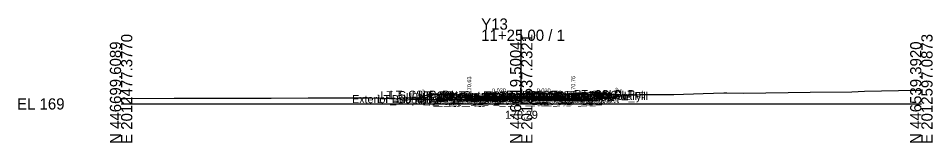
# Model space of a CAD drawing. Extents: x -26 to 1403, y -10 to 4517.
# Drawn here: x -25.7 to 202.8, y 2490.3 to 2521.4 of the extents above; entities that cross this region are included whole.
import ezdxf

# ---------------------------------------------------------------- set-up
doc = ezdxf.new("R2010")
doc.units = 0
for name, color, linetype in [('Default', 7, 'Continuous'), ('Exist CMT Pavement', 7, 'Continuous'), ('Exist Cross Section Cell', 7, 'Continuous'), ('Exist XS Center Line Elevation Label', 7, 'Continuous'), ('Exist XS Ground Line', 7, 'Continuous'), ('Prop CMT Conc Surface', 7, 'Continuous'), ('Prop CMT Concrete Structures', 7, 'Continuous'), ('Prop CMT Pvmt Course 1', 7, 'Continuous'), ('Prop CMT Pvmt Course 1 CG', 7, 'Continuous'), ('Prop CMT Pvmt Course 1 Wedge', 7, 'Continuous'), ('Prop CMT Pvmt Course 2', 7, 'Continuous'), ('Prop CMT Pvmt Course 2 Wedge', 7, 'Continuous'), ('Prop CMT Pvmt Course 3', 7, 'Continuous'), ('Prop CMT Pvmt Course 3 Wedge', 7, 'Continuous'), ('Prop CMT Pvmt Surface', 7, 'Continuous'), ('Prop CMT Pvmt Wedge Surface 1', 7, 'Continuous'), ('Prop CMT Pvmt Wedge Surface 2', 7, 'Continuous'), ('Prop CMT Pvmt Wedge Surface 3', 7, 'Continuous'), ('Prop CMT Slope Grass', 7, 'Continuous'), ('Prop CMT Subgrade Earthwork', 7, 'Continuous'), ('Prop XS Earthwork Shape', 7, 'Continuous'), ('Prop XS Hydro Elevations', 7, 'Continuous'), ('Prop XS SE Text', 7, 'Continuous'), ('Prop XS Side Slope Text', 7, 'Continuous'), ('Scratch_Level_0', 7, 'Continuous')]:
    doc.layers.add(name, color=color, linetype=linetype)

msp = doc.modelspace()

# ---------------------------------------------------------------- linework, layer by layer
at = {"layer": 'Exist CMT Pavement'}
for points in [[(100, 2501.29), (99.91, 2501.29), (94.09, 2501.06), (90, 2500.86)], [(100, 2501.29), (105.87, 2501.1), (110, 2500.94)]]:
    msp.add_lwpolyline(points, dxfattribs=at)
at = {"layer": 'Exist Cross Section Cell'}
for p, q in [((100, 2500), (100, 2518.56)), ((0, 2500), (100, 2500)), ((100, 2500), (200, 2500))]:
    msp.add_line(p, q, dxfattribs=at)
at = {"layer": 'Exist XS Ground Line'}
msp.add_lwpolyline([(0, 2501.37), (0.82, 2501.37), (1.32, 2501.37), (13.3, 2501.4), (18.7, 2501.42), (29.61, 2501.43), (35.4, 2501.43), (37.51, 2501.44), (46.73, 2501.48), (50.75, 2501.49), (52.11, 2501.48), (62.49, 2501.48), (72.37, 2501.22), (76.33, 2501.13), (87.5, 2501.1), (89.27, 2500.83), (99.91, 2501.29), (111.43, 2500.89), (112.97, 2501.14), (121.28, 2501.71), (125.66, 2502.07), (129.94, 2502.35), (135.66, 2502.38), (137.08, 2502.38), (138.15, 2502.39), (145.5, 2502.6), (150.63, 2502.73), (151.37, 2502.75), (155.65, 2502.72), (172.22, 2502.92), (182.64, 2503.02), (185.79, 2503.16), (194.25, 2503.35), (200, 2503.42)], dxfattribs=at)
at = {"layer": 'Prop CMT Conc Surface'}
for points in [[(87, 2501.63), (87, 2502.13), (86.5, 2502.13)], [(89, 2501.75), (87, 2501.63)], [(111, 2501.86), (113, 2501.76)], [(113, 2501.76), (113, 2502.26), (113.5, 2502.26)]]:
    msp.add_lwpolyline(points, dxfattribs=at)
at = {"layer": 'Prop CMT Concrete Structures'}
for points in [[(89, 2501.75), (87, 2501.63), (87, 2502.13), (86.5, 2502.13)], [(86.5, 2502.13), (86.5, 2501.12), (89, 2501.17)], [(89, 2501.17), (89, 2501.75)], [(111, 2501.86), (113, 2501.76), (113, 2502.26), (113.5, 2502.26)], [(113.5, 2502.26), (113.5, 2501.25), (111, 2501.28)], [(111, 2501.28), (111, 2501.86)]]:
    msp.add_lwpolyline(points, dxfattribs=at)
at = {"layer": 'Prop CMT Pvmt Course 1'}
for points in [[(100, 2501.97), (89, 2501.75)], [(89, 2501.75), (89, 2501.5)], [(89, 2501.5), (90, 2501.52)], [(90, 2501.65), (100, 2501.85)], [(90, 2501.52), (90, 2501.65)], [(100, 2501.72), (100, 2501.97)], [(100, 2501.97), (111, 2501.86)], [(100, 2501.72), (100, 2501.97)], [(100, 2501.85), (100, 2501.72), (100, 2501.72)], [(110, 2501.75), (100, 2501.85)], [(100, 2501.85), (100, 2501.72), (100, 2501.72)], [(110, 2501.62), (110, 2501.75)], [(111, 2501.61), (110, 2501.62)], [(111, 2501.86), (111, 2501.61)]]:
    msp.add_lwpolyline(points, dxfattribs=at)
at = {"layer": 'Prop CMT Pvmt Course 1 CG'}
for points in [[(89, 2501.17), (86, 2501.11), (85.66, 2500.77)], [(85.66, 2500.77), (89, 2500.84)], [(89, 2500.84), (89, 2501.17)], [(111, 2501.28), (114, 2501.25), (114.34, 2500.91)], [(111, 2500.95), (111, 2501.28)], [(114.34, 2500.91), (111, 2500.95)]]:
    msp.add_lwpolyline(points, dxfattribs=at)
at = {"layer": 'Prop CMT Pvmt Course 1 Wedge'}
for points in [[(90, 2501.65), (94.09, 2501.73), (99.91, 2501.85), (100, 2501.85)], [(100, 2501.72), (99.91, 2501.72), (94.09, 2501.6), (90, 2501.52)], [(90, 2501.52), (90, 2501.65)], [(100, 2501.85), (100, 2501.72)], [(100, 2501.85), (105.87, 2501.79), (110, 2501.75)], [(100, 2501.72), (100, 2501.85)], [(110, 2501.62), (105.87, 2501.66), (100, 2501.72)], [(110, 2501.75), (110, 2501.62)]]:
    msp.add_lwpolyline(points, dxfattribs=at)
at = {"layer": 'Prop CMT Pvmt Course 2'}
for points in [[(90, 2501.52), (89, 2501.5)], [(89, 2501.5), (89, 2501.17)], [(89, 2501.17), (90, 2501.19)], [(90, 2501.19), (90, 2501.52)], [(110, 2501.29), (110, 2501.62)], [(110, 2501.62), (111, 2501.61)], [(111, 2501.28), (110, 2501.29)], [(111, 2501.61), (111, 2501.28)]]:
    msp.add_lwpolyline(points, dxfattribs=at)
at = {"layer": 'Prop CMT Pvmt Course 2 Wedge'}
for points in [[(90, 2501.52), (94.09, 2501.6), (99.91, 2501.72), (100, 2501.72)], [(90, 2501.19), (90, 2501.52)], [(100, 2501.39), (99.91, 2501.39), (94.09, 2501.27), (90, 2501.19)], [(100, 2501.72), (100, 2501.39)], [(100, 2501.72), (105.87, 2501.66), (110, 2501.62)], [(100, 2501.39), (100, 2501.72)], [(110, 2501.29), (105.87, 2501.33), (100, 2501.39)], [(110, 2501.62), (110, 2501.29)]]:
    msp.add_lwpolyline(points, dxfattribs=at)
at = {"layer": 'Prop CMT Pvmt Course 3'}
for points in [[(90, 2501.19), (89, 2501.17)], [(89, 2501.17), (89, 2500.84)], [(89, 2500.84), (90, 2500.86)], [(90, 2500.86), (90, 2501.19)], [(110, 2501.29), (111, 2501.28)], [(110, 2500.96), (110, 2501.29)], [(111, 2500.95), (110, 2500.96)], [(111, 2501.28), (111, 2500.95)]]:
    msp.add_lwpolyline(points, dxfattribs=at)
at = {"layer": 'Prop CMT Pvmt Course 3 Wedge'}
for points in [[(90, 2501.19), (94.09, 2501.27), (99.91, 2501.39), (100, 2501.39)], [(100, 2501.29), (99.91, 2501.29), (94.09, 2501.06), (90, 2500.87)], [(90, 2500.87), (90, 2501.19)], [(100, 2501.39), (100, 2501.29)], [(100, 2501.39), (105.87, 2501.33), (110, 2501.29)], [(100, 2501.29), (100, 2501.39)], [(110, 2500.94), (105.87, 2501.1), (100, 2501.29)], [(110, 2501.29), (110, 2500.94)]]:
    msp.add_lwpolyline(points, dxfattribs=at)
at = {"layer": 'Prop CMT Pvmt Surface'}
for points in [[(100, 2501.97), (89, 2501.75)], [(100, 2501.97), (111, 2501.86)]]:
    msp.add_lwpolyline(points, dxfattribs=at)
at = {"layer": 'Prop CMT Pvmt Wedge Surface 1'}
for points in [[(89, 2501.5), (89, 2501.75)], [(90, 2501.52), (89, 2501.5)], [(100, 2501.85), (90, 2501.65)], [(90, 2501.65), (90, 2501.52)], [(100, 2501.85), (110, 2501.75)], [(110, 2501.75), (110, 2501.62)], [(110, 2501.62), (111, 2501.61)], [(111, 2501.61), (111, 2501.86)]]:
    msp.add_lwpolyline(points, dxfattribs=at)
at = {"layer": 'Prop CMT Pvmt Wedge Surface 2'}
for points in [[(89, 2501.5), (89, 2501.75)], [(100, 2501.72), (89, 2501.5)], [(100, 2501.72), (111, 2501.61)], [(111, 2501.61), (111, 2501.86)]]:
    msp.add_lwpolyline(points, dxfattribs=at)
at = {"layer": 'Prop CMT Pvmt Wedge Surface 3'}
for points in [[(89, 2501.17), (89, 2501.75)], [(100, 2501.39), (89, 2501.17)], [(100, 2501.39), (111, 2501.28)], [(111, 2501.28), (111, 2501.86)]]:
    msp.add_lwpolyline(points, dxfattribs=at)
at = {"layer": 'Prop CMT Slope Grass'}
for points in [[(113.5, 2502.26), (123, 2502.45), (124.45, 2501.97)], [(86.5, 2502.13), (77, 2502.32), (73.6, 2501.19)]]:
    msp.add_lwpolyline(points, dxfattribs=at)
at = {"layer": 'Prop CMT Subgrade Earthwork'}
for points in [[(89, 2500.84), (85.66, 2500.77), (84.25, 2502.18)], [(90, 2500.86), (89, 2500.84)], [(90, 2500.86), (90, 2500.86)], [(110, 2500.96), (110, 2500.94)], [(110, 2500.96), (111, 2500.95)], [(111, 2500.95), (114.34, 2500.91), (115.73, 2502.31)]]:
    msp.add_lwpolyline(points, dxfattribs=at)
at = {"layer": 'Prop XS Earthwork Shape'}
for points in [[(121.28, 2501.71), (124.45, 2501.97), (123, 2502.45), (115.73, 2502.31), (114.68, 2501.26)], [(76.33, 2501.13), (85.32, 2501.11), (84.25, 2502.18), (77, 2502.32), (73.6, 2501.19)], [(85.32, 2501.11), (87.5, 2501.1), (89.21, 2500.84), (89, 2500.84), (85.66, 2500.77)], [(89.27, 2500.83), (90, 2500.86), (89.21, 2500.84)], [(94.09, 2501.06), (90, 2500.86), (99.91, 2501.29)], [(100, 2501.29), (105.87, 2501.1), (110, 2500.94), (99.91, 2501.29)], [(110, 2500.96), (110, 2500.94), (111.43, 2500.89), (111.75, 2500.94), (111, 2500.95)], [(114.34, 2500.91), (114.68, 2501.26), (112.97, 2501.14), (111.75, 2500.94)]]:
    msp.add_lwpolyline(points, close=True, dxfattribs=at)

# ---------------------------------------------------------------- texts
at = {"layer": 'Default'}
msp.add_text('-', height=0.0001, dxfattribs=at).set_placement((0, 2500))
at = {"layer": 'Exist Cross Section Cell'}
for s, p in [('Y13', (90, 2518.56)), ('11+25.00 / 1', (90, 2515.76)), ('EL 169', (-26, 2498.6))]:
    msp.add_text(s, height=2.8, dxfattribs=at).set_placement(p)
for s, p in [('E 2012477.3770', (2.8, 2490)), ('E 2012537.2321', (102.8, 2490)), ('E 2012597.0873', (202.8, 2490)), ('N 446699.6089', (0, 2490)), ('N 446619.5004', (100, 2490)), ('N 446539.3920', (200, 2490))]:
    msp.add_text(s, height=2.8, rotation=90, dxfattribs=at).set_placement(p)
at = {"layer": 'Exist XS Center Line Elevation Label'}
msp.add_text('170.29', height=2, dxfattribs=at).set_placement((95.97, 2496.29))
at = {"layer": 'Prop XS Hydro Elevations'}
for s, p in [('170.63', (87.5, 2502.63)), ('170.76', (113.5, 2502.76))]:
    msp.add_text(s, height=1, rotation=90, dxfattribs=at).set_placement(p)
at = {"layer": 'Prop XS SE Text'}
for s, rotation, p in [('0.020', 1.1458, (92.73, 2502.83)), ('0.010', 359.4271, (103.88, 2502.93))]:
    msp.add_text(s, height=1, rotation=rotation, dxfattribs=at).set_placement(p)
at = {"layer": 'Prop XS Side Slope Text'}
for rotation, p in [(18.4332, (74.3, 2502.21)), (341.5668, (123.21, 2503.17))]:
    msp.add_text('3:1', height=1, rotation=rotation, dxfattribs=at).set_placement(p)
at = {"layer": 'Scratch_Level_0'}
for s, p in [('LT_Sub_Trench_Out_DLT', (64.82, 2501.18)), ('LT_CSLP_Pnt', (67.17, 2501.32)), ('LT_CG_Top_Face', (74.26, 2501.13)), ('LT_CG_Top_BOC', (74.78, 2501.13)), ('LT_CG_Top_Gut', (75.24, 2500.63)), ('LT_PV2_OEOT', (79.17, 2500.5)), ('LT_PV2_OEEOP', (79.31, 2500.52)), ('LT_PV1_OEOT', (79.74, 2500.75)), ('LT_PV1_OEEOP', (79.87, 2500.65)), ('RT_PV2_IEEOP', (89.91, 2500.72)), ('LT_PV2_IEEOP', (89.95, 2500.72)), ('RT_PV1_IEEOP', (90.47, 2500.85)), ('LT_PV1_IEEOP', (90.52, 2500.85)), ('PV2_PGL', (93.91, 2500.72)), ('PV1_PGL', (94.47, 2500.97)), ('RT_Sub_Trench_Out_DLT', (96.25, 2501.31)), ('RT_PV2_OEEOP', (99.26, 2500.62)), ('RT_PV1_OEEOP', (99.83, 2500.75)), ('RT_CG_Top_Face', (100.21, 2501.26)), ('RT_PV2_OEOT', (101.13, 2500.61)), ('RT_CG_Top_Gut', (101.19, 2500.76)), ('RT_PV1_OEOT', (101.69, 2500.86)), ('RT_CG_Top_BOC', (101.74, 2501.26)), ('Exterior Boundary', (108.59, 2500.97)), ('RT_CSLP_Pnt', (113.13, 2501.45)), ('RT_Slope_Fill', (114.92, 2500.97)), ('Exterior Boundary', (57.73, 2500.19)), ('LT_Slope_Fill', (64.11, 2500.19)), ('LT_CG1_Shelf_Out', (72.55, 2500.11)), ('LT_CG_Bot_BOC', (74.81, 2500.12)), ('LT_PV_Sub_Tie_Out', (74.96, 2499.87)), ('LT_Sub_OEOP', (75.77, 2499.77)), ('LT_PV_OEEOP_EG', (77.54, 2499.87)), ('LT_CG_Bot_IE', (78.91, 2500.17)), ('LT_Sub_OEOT', (79.08, 2499.84)), ('LT_PV3_OEOT', (79.17, 2500.17)), ('LT_Sub_OEEOP', (79.21, 2499.86)), ('LT_PV3_OEEOP', (79.31, 2500.19)), ('RT_PV_IEEOP_EG', (88.14, 2500.29)), ('LT_PV_IEEOP_EG', (88.19, 2500.29)), ('RT_PV3_IEEOP', (89.91, 2500.39)), ('LT_PV3_IEEOP', (89.95, 2500.39)), ('RT_PV_Sub_Tie_Out', (94.88, 2499.94)), ('RT_PV_OEEOP_EG', (97.5, 2499.94)), ('RT_Sub_OEEOP', (99.17, 2499.96)), ('RT_PV3_OEEOP', (99.26, 2500.29)), ('RT_CG1_Shelf_Out', (100.5, 2500.25)), ('RT_CG_Bot_IE', (100.87, 2500.28)), ('RT_Sub_OEOT', (101.03, 2499.95)), ('RT_PV3_OEOT', (101.13, 2500.28)), ('RT_CG_Bot_BOC', (101.77, 2500.25)), ('RT_Sub_OEOP', (104.4, 2499.91))]:
    msp.add_text(s, height=2, dxfattribs=at).set_placement(p)

doc.saveas('drawing.dxf')
